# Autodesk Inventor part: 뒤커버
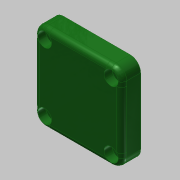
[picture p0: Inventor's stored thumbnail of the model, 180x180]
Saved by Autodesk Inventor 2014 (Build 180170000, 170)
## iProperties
Created: 2018-07
Part Number: 뒤커버
Material: 알루미늄 6061
Document SubType Name: Modeling
Designer: mduedu
Density: 1 g/cm^3
Appearance: 매끄러움 - 짙은 산림 녹색
Author: mduedu
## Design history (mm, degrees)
sketch "스케치1"
  geometry: C1 r 16 at (0, 0); 1 further point
  constraints: 1 centre point, 1 coincident
  dimensions: "d0" = 32 diameter of C1
extrude "돌출1" new body sketch "스케치1" distance "d1" = 3; taper "d2" = 0 deg
sketch "스케치2"
  geometry: L1 (-25, -25)-(25, -25); L2 (25, -25)-(25, 25); L3 (25, 25)-(-25, 25); L4 (-25, 25)-(-25, -25); L5 (-25, -25)-(25, 25); L6 (25, -25)-(-25, 25); 1 further point
  constraints: 12 end point, 2 midpoint, 2 parallel, 1 horizontal, 1 perpendicular
  dimensions: "d3" = 50 distance of L3.end L2.end; "d4" = 50 distance of L2.end L1.end
extrude "돌출2" join sketch "스케치2" distance "d5" = 11; taper "d6" = 0 deg
hole "구멍1" diameter "d9" = 25; stored, may be unused: countersink angle "d13" = 90 deg, drill point angle "d15" = 0 deg; dims "d7" = 10, "d8" = 10, "d10" = 6, "d11" = 4, "d12" = 2, "d14" = 3
fillet "모깎기2" dims "d26" = 3
fillet "모깎기3" dims "d27" = 6
sketch "스케치5"
  geometry: L1 (25, -19)-(25, 19) reference; L2 (19, 25)-(-19, 25) reference; L3 (-25, 19)-(-25, -19) reference; L4 (-19, -25)-(19, -25) reference; A1 r 6 centre (19, -19) between (19, -25) and (25, -19) reference; A2 r 6 centre (19, 19) between (25, 19) and (19, 25) reference; A3 r 6 centre (-19, 19) between (-19, 25) and (-25, 19) reference; A4 r 6 centre (-19, -19) between (-25, -19) and (-19, -25) reference; 5 further points
  constraints: 4 coincident
hole "구멍2" sketch "스케치5" at (-19, 19), (19, 19), (19, -19), (-19, -19) diameter "d28" = 4.5; stored, may be unused: countersink angle "d32" = 90 deg, drill point angle "d34" = 0 deg; dims "d29" = 6, "d30" = 8, "d31" = 4.6, "d33" = 3
fillet "모깎기4" dims "d35" = 3
chamfer "모따기2" distance "d36" = 1; stored, may be unused: second distance "d37" = 2, angle "d38" = 45 deg
node "솔리드1"
node "투영된 루프1"
